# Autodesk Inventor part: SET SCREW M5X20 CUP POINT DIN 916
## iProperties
IsCustomPart: 1
Created: 2006-02
Part Number: SET SCREW M5X20 CUP POINT DIN 916
Material: Steel, Mild
Description: Hexagon Socket Set Screw
Document SubType Name: Modeling
Standard: DIN 916
Designer: Andy Moles
Standards Organization: DIN
Language: en-US
Size Designation: M5  x  20
Categories: <MemberInstance><Categories><Category DisplayName="Fasteners" InternalName="e4da775c-781d-43d5-af7c-5136215cf5a6" Mnemonic="FSTN"><Category DisplayName="Bolts"
Density: 1 g/cm^3
Author: Andy Moles
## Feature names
1. Body [Revolution]
2. Slot [Extrusion]
3. Chamfer1
4. Chamfer2
